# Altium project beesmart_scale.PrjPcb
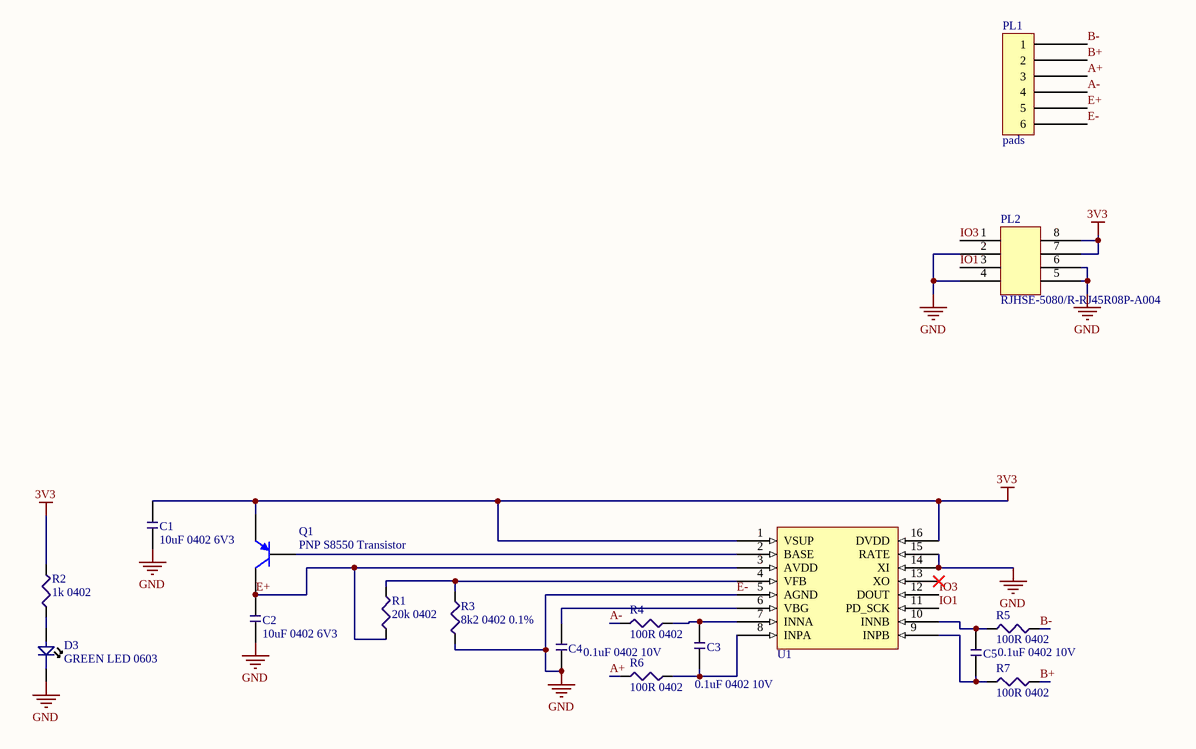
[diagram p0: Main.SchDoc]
GlobalCompanyName: na; GlobalDrawnBy: Mogens Groth Nicolaisen; GlobalProjectName: BeeSMART Scale; GlobalProjectRevision: 1.0
1 sheet, 17 parts. Net scope: hierarchical (ports join the sheet entries above them; power ports are global).
Board file: beesmart_scale.PcbDoc

## Sheet Main.SchDoc: BeeSMART Scale
size A3; DrawnBy: Mogens Groth Nicolaisen; DocumentNumber: 1; Revision: 1.0; SheetNumber: 1; SheetTotal: 1

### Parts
C1  10uF 0402 6V3  [CAP_0402]
C2  10uF 0402 6V3  [CAP_0402]
C3  0.1uF 0402 10V  [CAP_0402]
C4  0.1uF 0402 10V  [CAP_0402]
C5  0.1uF 0402 10V  [CAP_0402]
D3  GREEN LED 0603  [0603 LED]
PL1  pads  [6-pin 2.54mm header - female right angle]
PL2  RJHSE-5080/R-RJ45R08P-A004  [AMPHENOL RJHSE-5080]
Q1  PNP S8550 Transistor  [SOT95P245X110-3N]
R1  20k 0402  [RES_0402]
R2  1k 0402  [RES_0402]
R3  8k2 0402 0.1%  [RES_0402]
R4  100R 0402  [RES_0402]
R5  100R 0402  [RES_0402]
R6  100R 0402  [RES_0402]
R7  100R 0402  [RES_0402]
U1  HX711  [TSOP127P600X160-16N]  (value not drawn)

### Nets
3V3: C1.2 PL2.7 PL2.8 Q1.1(E) R2.2 U1.1(VSUP) U1.16(DVDD)
E-: C1.1 C2.1 C4.2 D3.2 PL1.6 PL2.2 PL2.4 PL2.5 PL2.6 R3.1 U1.5(AGND) U1.14(XI) U1.15(RATE)  [also labelled GND]
A+: PL1.3 R6.2
A-: PL1.4 R4.2
B+: PL1.2 R7.1
B-: PL1.1 R5.1
E+: C2.2 PL1.5 Q1.3(C) R1.1 U1.3(AVDD)
IO1: PL2.3 U1.11(PD_SCK)
IO3: PL2.1 U1.12(DOUT)
NetC3_1: C3.1 R4.1 U1.7(INNA)
NetC3_2: C3.2 R6.1 U1.8(INPA)
NetC4_1: C4.1 U1.6(VBG)
NetC5_1: C5.1 R5.2 U1.10(INNB)
NetC5_2: C5.2 R7.2 U1.9(INPB)
NetD3_1: D3.1 R2.1
NetQ1_2: Q1.2(B) U1.2(BASE)
NetR1_2: R1.2 R3.2 U1.4(VFB)

Not connected (* = marked no-connect by the designer): U1 13(XO)*

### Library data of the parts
C1 C2 = CMP-00011-3: 10uF 20% 0402 6V3 X6S
C3-C5 = CMP-00101-1: 0.1uF 0402 10V X7R 10%; Value: 100 nF
D3 = CMP-008-0000-1: SMD GREEN WATER CLEAR; Mfg. Part Number: APT1608SGC
PL1 = CMP-003-0023-0.1: Pin Header 6-pin 2.54mm female right angle
PL2 = CMP-003-0022-0.1: CONN MOD JACK 8P8C R/A UNSHLD; Shielding: Unshielded; Gender: Female; Current Rating: 1.5A; Voltage Rating: 125V; Contact Resistance: 20mR; Connector Type: Jack, RJ45; Number of Ports: 1; Direction: Up; Number of Contacts: 8; Pitch: 2.03mm
Q1 = CMP-014-0022-0.0: S8550; Part no.: C105432
R1 = CMP-001-0026-3: RES SMD 22K OHM 1% 1/16W 0402; Mfg. Part Number: RMCF0402FT22K0
R2 = CMP-001-0025-3: RES SMD 1K OHM 1% 1/16W 0402; Mfg. Part Number: CRG0402F1K0
R3 = CMP-001-0038-2: TE CONNECTIVITY / NEOHM         CPF0402B8K2E1             SMD Chip Resistor, Thin Film, 8.2 kohm, 25 V, 0402 [1005 Metric], 63 mW,  0.1%, CPF Series; Power: 1/16 W
R4-R7 = CMP-001-0001-5: 100R 1% 0402 63mW
U1 = CMP-00183-2: 24-Bit Analog-to-Digital Converter (ADC) for Weigh Scales; Part no: C6705483

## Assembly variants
Default: not fitted J1 PL2 PL2 PL3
